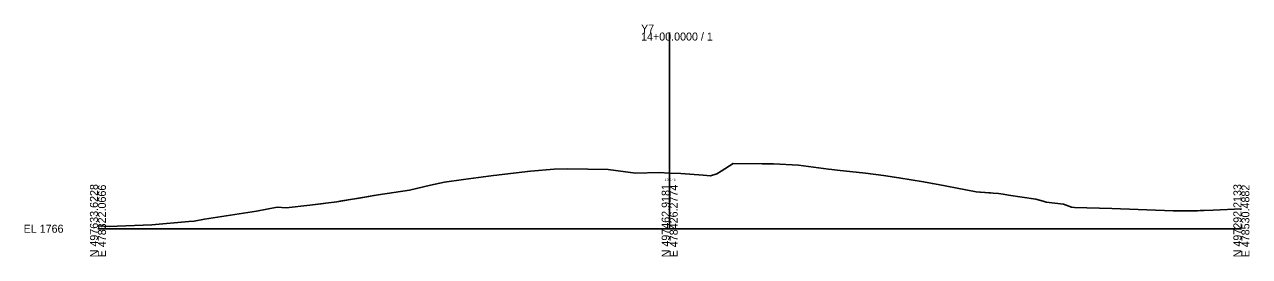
# Model space of a CAD drawing. Extents: x -26 to 403, y -10 to 4071.
# Drawn here: x -25.7 to 402.8, y 3990.3 to 4071.4 of the extents above; entities that cross this region are included whole.
import ezdxf

# ---------------------------------------------------------------- set-up
doc = ezdxf.new("R2010")
doc.units = 0
for name, color, linetype in [('Exist Cross Section Cell', 7, 'Continuous'), ('Exist XS Center Line Elevation Label', 7, 'Continuous'), ('Exist XS Ground Line', 7, 'Continuous'), ('Scratch_Level_5', 7, 'Continuous')]:
    doc.layers.add(name, color=color, linetype=linetype)

msp = doc.modelspace()

# ---------------------------------------------------------------- linework, layer by layer
at = {"layer": 'Exist Cross Section Cell'}
for p, q in [((200, 4000), (200, 4068.55)), ((0, 4000), (200, 4000)), ((200, 4000), (400, 4000))]:
    msp.add_line(p, q, dxfattribs=at)
at = {"layer": 'Exist XS Ground Line'}
msp.add_lwpolyline([(0, 4000.99), (4.2, 4000.73), (6.72, 4000.85), (18.86, 4001.41), (31.74, 4002.5), (33.66, 4002.66), (37.26, 4003.31), (55.41, 4006.19), (62.73, 4007.51), (65.81, 4007.28), (74.07, 4008.21), (78.03, 4008.68), (79.7, 4008.88), (83.56, 4009.4), (84.64, 4009.58), (88.24, 4010.19), (90.64, 4010.6), (94.73, 4011.29), (96.55, 4011.6), (98.06, 4011.85), (108.96, 4013.45), (116.34, 4015.22), (121.18, 4016.27), (127.86, 4017.15), (138.32, 4018.55), (139.57, 4018.7), (140.38, 4018.83), (151.29, 4020.11), (159.57, 4020.86), (164.21, 4020.94), (178.5, 4020.66), (188.1, 4019.47), (196.36, 4019.62), (200, 4019.46), (203.89, 4019.28), (211.71, 4018.76), (214.28, 4018.49), (216.5, 4019.23), (217.99, 4020.17), (222.19, 4022.85), (232.34, 4022.72), (234.47, 4022.7), (236.35, 4022.65), (245.04, 4022.24), (255.55, 4020.83), (256.76, 4020.65), (258.65, 4020.44), (268.48, 4019.36), (274.75, 4018.62), (280.2, 4017.84), (288.74, 4016.34), (291.91, 4015.78), (293.94, 4015.44), (303.63, 4013.54), (307.24, 4012.87), (308.54, 4012.77), (312.18, 4012.5), (313.14, 4012.43), (315.01, 4012.3), (316.69, 4012.04), (318.55, 4011.76), (328.11, 4010.35), (330.68, 4009.6), (331.71, 4009.3), (337.8, 4008.54), (340.62, 4007.56), (341.57, 4007.46), (354.66, 4007.08), (376.09, 4006.22), (383.74, 4006.31), (384.65, 4006.28), (385.59, 4006.4), (386.98, 4006.42), (390.11, 4006.52), (400, 4006.91)], dxfattribs=at)
at = {"layer": 'Scratch_Level_5'}
msp.add_lwpolyline([(74.07, 4008.21), (79.7, 4008.88), (83.56, 4009.4), (98.06, 4011.85), (108.96, 4013.45), (116.34, 4015.22), (121.18, 4016.27), (127.86, 4017.15), (138.32, 4018.55), (139.57, 4018.7), (140.38, 4018.83), (151.29, 4020.11), (159.57, 4020.86), (164.21, 4020.94), (178.5, 4020.66), (188.1, 4019.47), (196.36, 4019.62), (200, 4019.46), (203.89, 4019.28), (211.71, 4018.76), (214.28, 4018.49), (216.5, 4019.23), (217.99, 4020.17), (222.19, 4022.85), (232.34, 4022.72), (234.47, 4022.7), (236.35, 4022.65), (245.04, 4022.24), (255.55, 4020.83), (256.76, 4020.65), (258.65, 4020.44), (268.48, 4019.36), (274.75, 4018.62), (280.2, 4017.84), (288.74, 4016.34), (291.91, 4015.78), (293.94, 4015.44), (303.63, 4013.54), (307.24, 4012.87), (313.14, 4012.43)], dxfattribs=at)

# ---------------------------------------------------------------- texts
at = {"layer": 'Exist Cross Section Cell'}
for s, p in [('Y7', (190, 4068.55)), ('14+00.0000 / 1', (190, 4065.75)), ('EL 1766', (-26, 3998.6))]:
    msp.add_text(s, height=2.8, dxfattribs=at).set_placement(p)
for s, p in [('N 497633.6228', (0, 3990)), ('N 497462.9181', (200, 3990)), ('N 497292.2133', (400, 3990)), ('E 478322.0666', (2.8, 3990)), ('E 478426.2774', (202.8, 3990)), ('E 478530.4882', (402.8, 3990))]:
    msp.add_text(s, height=2.8, rotation=90, dxfattribs=at).set_placement(p)
at = {"layer": 'Exist XS Center Line Elevation Label'}
msp.add_text('1785.46', height=0.75, dxfattribs=at).set_placement((198.28, 4016.71))

doc.saveas('drawing.dxf')
